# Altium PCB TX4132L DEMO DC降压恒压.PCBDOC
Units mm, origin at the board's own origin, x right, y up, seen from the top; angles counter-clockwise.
Board outline 40.15 x 29.25 mm, 2 copper layers (TopLayer, BottomLayer); 27 components, 14 nets, 64 pads, 16 vias.
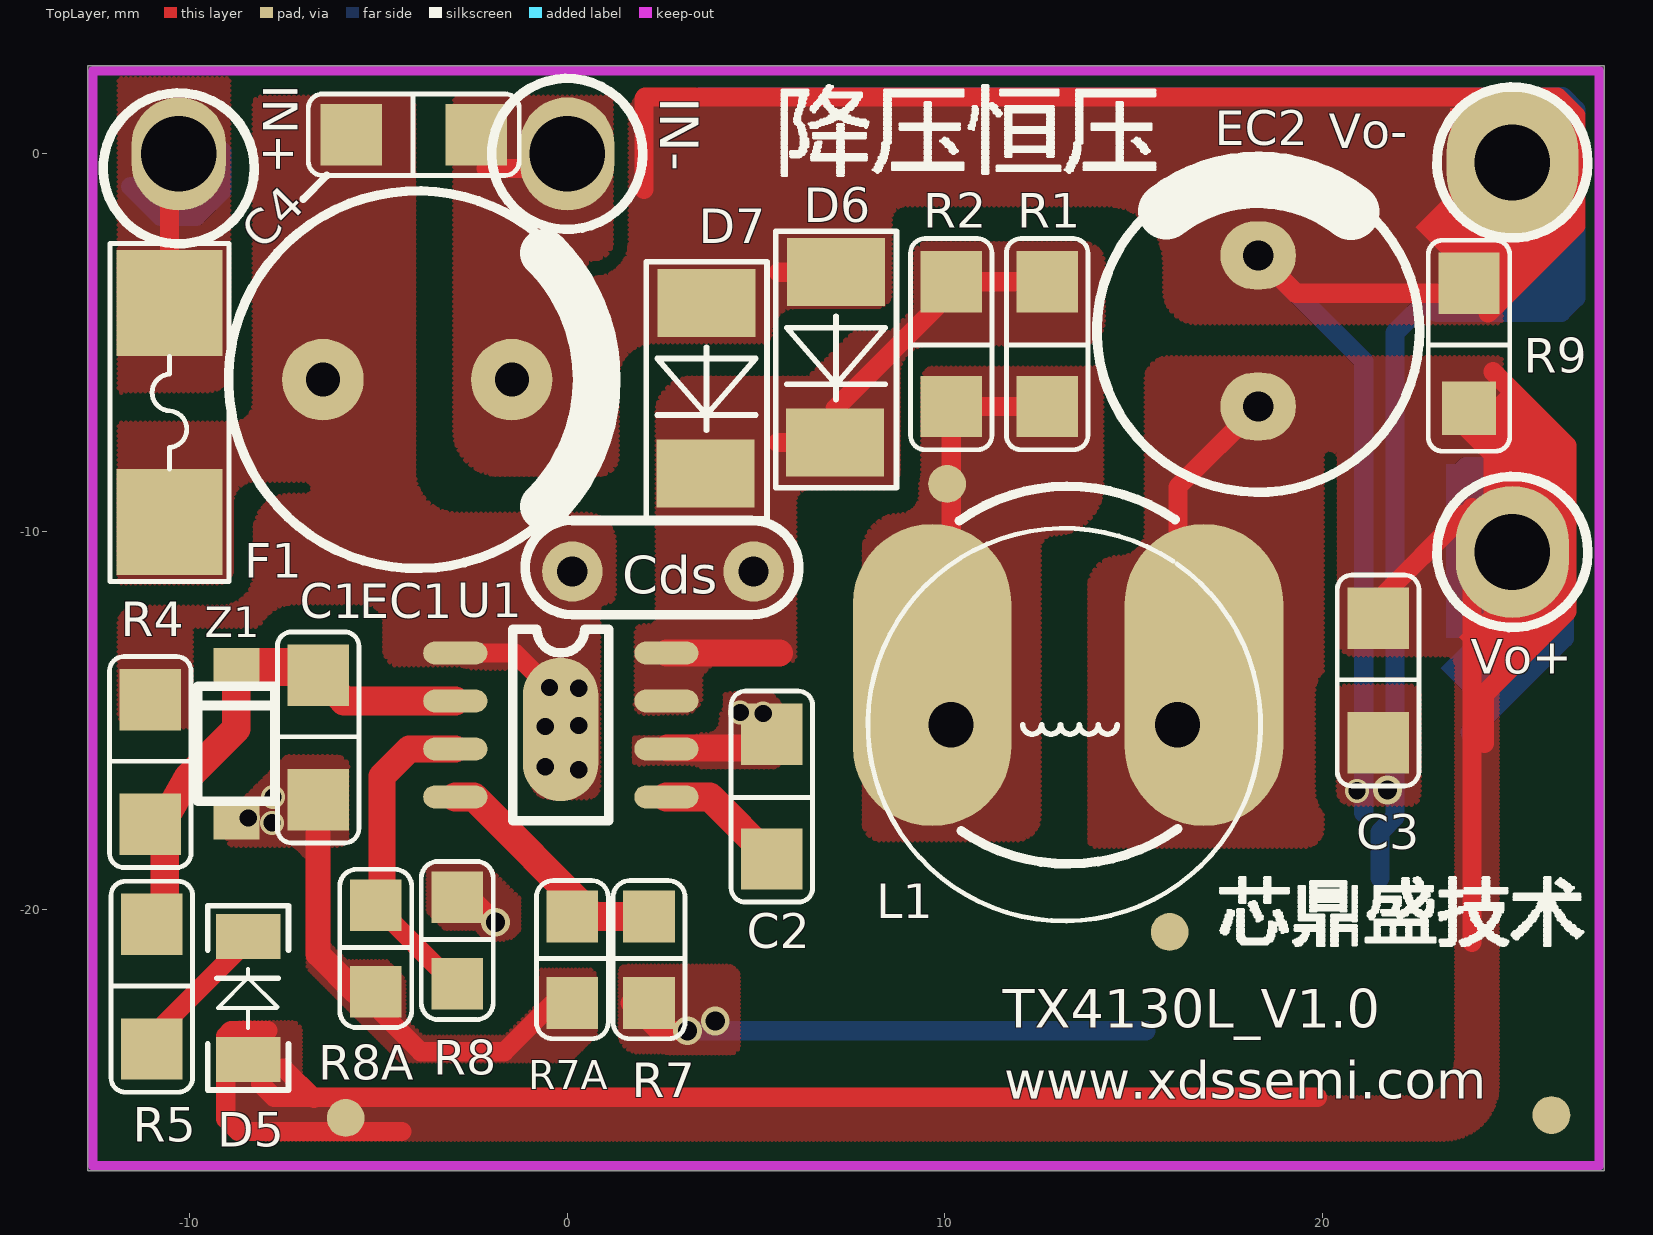
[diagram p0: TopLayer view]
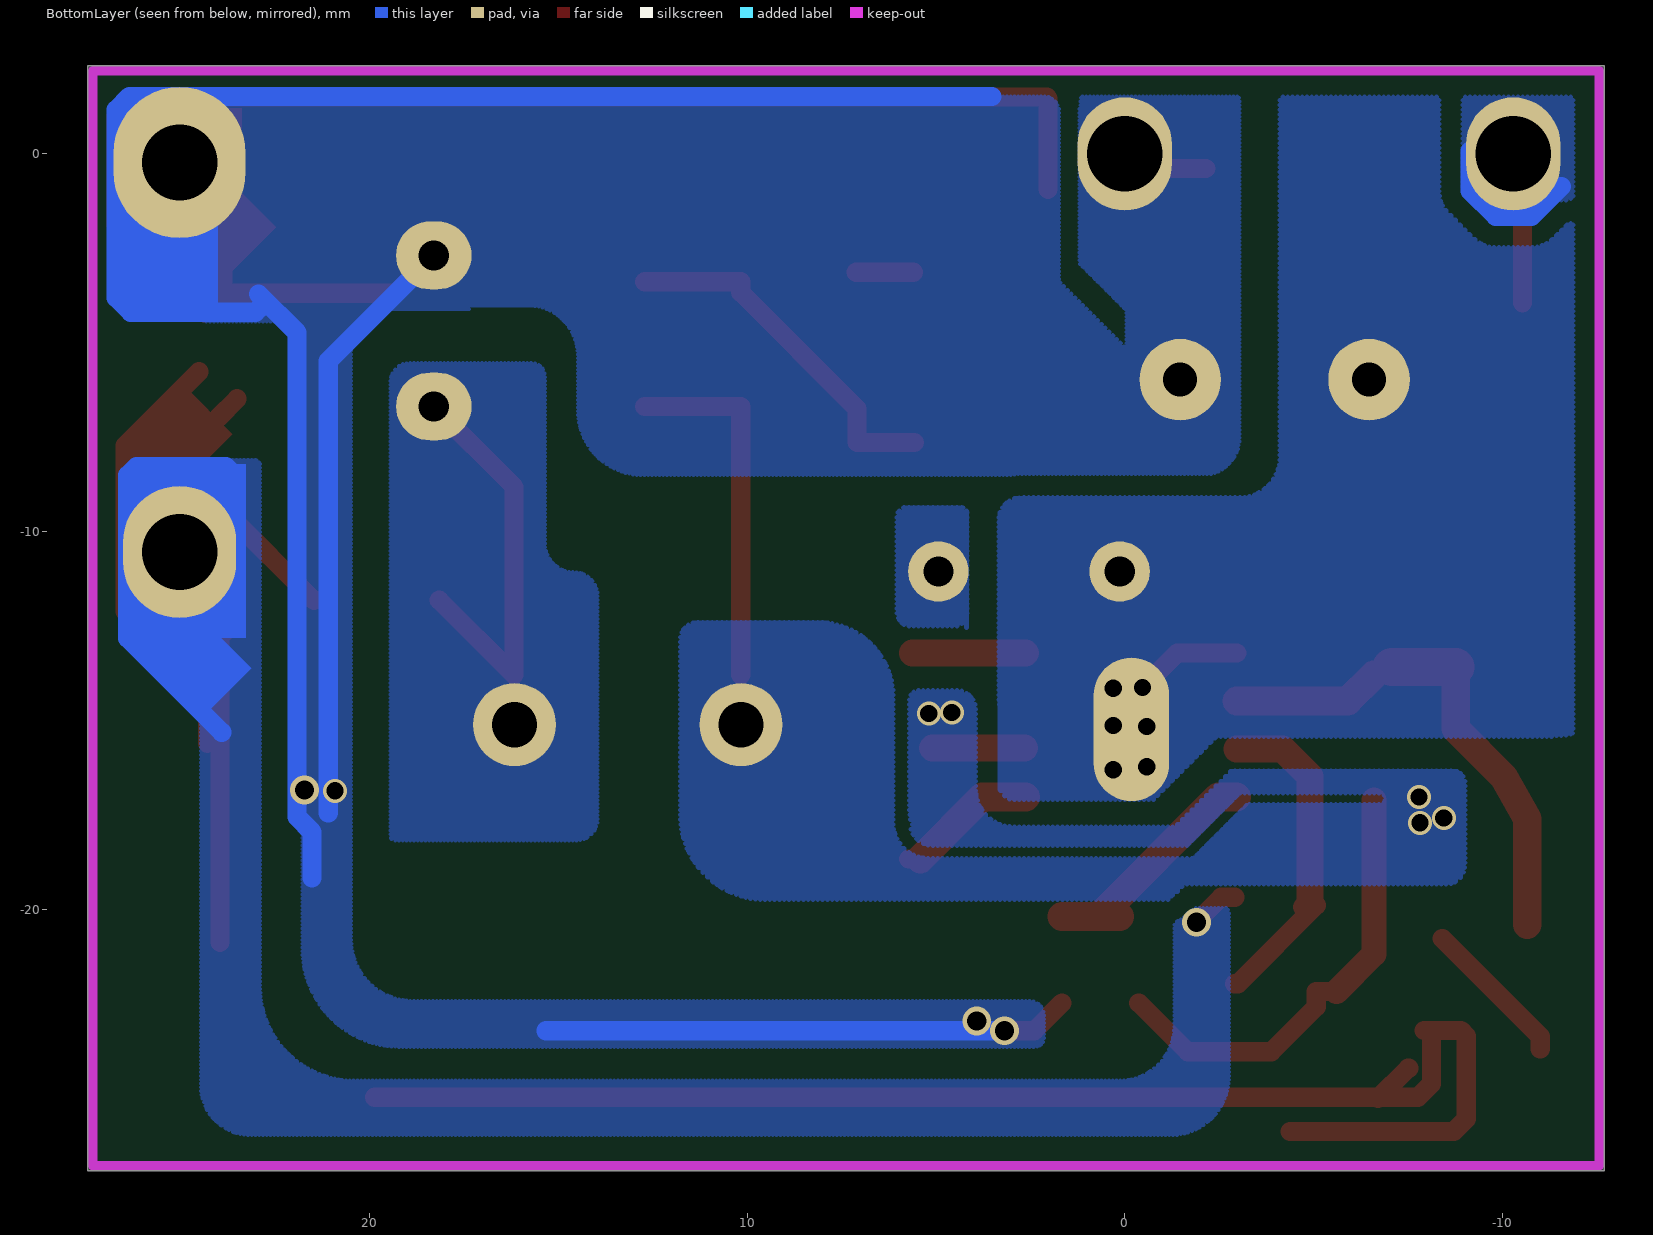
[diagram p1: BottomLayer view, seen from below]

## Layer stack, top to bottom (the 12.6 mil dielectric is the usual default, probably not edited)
TopLayer: signal copper 0.0356
Dielectric: dielectric 0.32, FR-4, Dk 4.8
BottomLayer: signal copper 0.0356

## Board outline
-12.692,-26.924 27.454,-26.924 27.454,2.33 -12.692,2.33

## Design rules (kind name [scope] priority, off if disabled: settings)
Clearance [All] p1: gap=0.508
ComponentClearance [All] p1 off: gap=0.254 collisioncheckmode=3 verticalgap=0.254 showdistances=FALSE
PolygonConnect [All] p1: connectstyle=Direct reliefconductorwidth=0.254 reliefentries=4 polygonreliefangle="90 Angle"
RoutingVias [All] p1: holewidth=0.711 width=1.27 viastyle="Through Hole" minholewidth=0.711 minwidth=1.27 maxholewidth=0.711 maxwidth=1.27
SilkscreenOverComponentPads [All] p1: minsilkscreentomaskgap=0.254
SolderMaskExpansion [All] p1: expansion=0.102
TestPointUsage [All] p1: valid=0 allowmultiple=FALSE
Testpoint [All] p1: side=15 testpointundercomponent=TRUE minsize=1.016 maxsize=2.54 preferedsize=1.524 minholesize=0.508 maxholesize=1.016 preferedholesize=0.813 testpointgrid=0.025 style=1023 order=0-112345678
Width [All] p1: maxlimit=0.508 minlimit=0.508 preferedwidth=0.508
22 further rules are at their usual default settings.

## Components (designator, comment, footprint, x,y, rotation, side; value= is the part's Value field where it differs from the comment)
C1 "" R1206#1 -6.596,-13.8 r0 top
C2 "" R1206#1 5.418,-18.669 r180 top
C3 "" R1206#1 21.471,-12.292 r0 top
C4 "" R1206#1 -5.715,0.508 r90 top
Cds "" CRCD 0.135,-11.057 r0 top
D5 "" S4148 -8.45,-23.975 r180 top
D6 "" SMB 7.12,-3.132 r270 top
D7 "" SMB 3.691,-3.945 r270 top
EC1 "" c10*16 -6.469,-5.977 r0 top
EC2 "" C8*12 18.296,-6.688 r0 top
F1 "" F05 -10.533,-3.945 r270 top
IN+ "" pad#1 -10.287,-0.381 r0 top
L1 "" CD105 9.66,-13.8 r0 top
R1 "" R1206#1 12.708,-6.688 r180 top
R2 "" R1206#1 10.168,-6.688 r180 top
R4 "" R1206#1 -11.041,-14.451 r0 top
R5 "" R1206#1 -11,-20.4 r0 top
R7 "" r0805 2.167,-20.193 r180 top
R7A "" r0805 0.135,-20.193 r180 top
R8 "" r0805 -2.913,-19.685 r180 top
R8A "" r0805 -5.072,-19.896 r180 top
R9 "" R1206#2 23.876,-3.429 r0 top
U1 "" SOP8 -2.964,-13.216 r90 top
Vo+ "" pad#2 25.027,-10.541 r90 top
Vo- "" pad#3 23.503,-0.227 r90 top
Z1 "" SOD123 -8.763,-17.653 r90 top
? "" L10*16 10.16,-15.113 r0 top

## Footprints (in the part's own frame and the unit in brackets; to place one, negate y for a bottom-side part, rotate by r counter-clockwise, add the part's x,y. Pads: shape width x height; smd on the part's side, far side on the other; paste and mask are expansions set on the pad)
C8*12 [mm]
  oval 2x1.8 hole 0.8: 1(0,0) 2(0,4)
  silkscreen extent -4.27,-2.27 4.27,6.27
c10*16 [mil]
  round 85 hole 35.43: 1(0,0) 2(196.85,0)
  silkscreen extent -98,-197 295,197
CD105 [mm]
  oval 4.2x8 smd: 1(0,0) 2(7.2,0)
  silkscreen extent 0.72,-5 6.51,5
CRCD [mm]
  round 1.6 hole 0.8: 1(0,0) 2(4.8,0)
  silkscreen extent -1.25,-1.15 6,1.35
F05 [mm]
  rect 2.8x2.8 smd: 1(0,0) 2(5.8,0)
  silkscreen extent -1.57,-1.57 7.37,1.57
L10*16 [mm]
  round 2.2 hole 1.2: 1(0,0) 2(6,0)
  silkscreen extent -2.2,-5.2 8.2,5.2
pad#1 [mm]
  oval 2.5x3 hole 2: 1(0,0.381)
pad#2 [mm]
  oval 3.5x3 hole 2: 1(0,0)
pad#3 [mm]
  oval 4x3.5 hole 2: 1(0,-1.524)
r0805 [mil]
  rect 54x54 smd: 1(0,0) 2(0,90)
  silkscreen extent -38,-38 38,128
R1206#1 [mil]
  rect 64x64 smd: 1(0,0) 2(0,-130)
  silkscreen extent -42,-175 42,45
R1206#2 [mil]
  rect 64x64 smd: 1(0,0)
  rect 56x56 smd: 2(0,-130)
  silkscreen extent -42,-175 42,45
S4148 [mil]
  rect 67x47 smd: 1(0,0) 2(0,-128)
  silkscreen extent -42,-160 42,32
SMB [mm]
  rect 1.8x2.6 smd: 1(0,0) 2(4.511,-0.031)
  silkscreen extent -1.09,-1.6 5.71,1.6
SOD123 [mm]
  rect 1x1.22 smd: 1(0,0) 2(4.064,0)
  silkscreen extent 0.51,-1.02 3.56,1.02
SOP8 [mil]
  oval 24x66.93 smd: 1(0,0) 2(-50,0) 3(-100,0) 4(-150,0) 5(-150,-220) 6(-100,-220) 7(-50,-220) 8(0,-220)
  round 27.56 on Top Overlay: ""(-22.13,-84.65)
  silkscreen extent -175,-160 25,-60

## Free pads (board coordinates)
  oval 2x3.8 all layers, no hole: 0(-0.178,-15.239)
  oval 2.5x3 hole 2: 0(0,0)
  round 1 smd: 1(-5.867,-25.527) 1(10.058,-8.738) 1(15.951,-20.599) 1(26.06,-25.451)

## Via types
v1: diameter 0.635, hole 0.457, TopLayer to BottomLayer, 6 vias
v2: diameter 0.889, hole 0.457, TopLayer to BottomLayer, 6 vias
v3: diameter 0.762, hole 0.508, TopLayer to BottomLayer, 4 vias

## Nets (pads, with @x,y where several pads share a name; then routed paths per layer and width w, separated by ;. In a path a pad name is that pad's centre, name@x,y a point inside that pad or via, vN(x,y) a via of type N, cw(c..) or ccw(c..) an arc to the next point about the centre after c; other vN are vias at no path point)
GND: C3.2 C4.2 D6.1 D7.1 EC1.2 EC2.2 pad.0@0,0 R7.2 R9.1 Vo-.1 | length 124.5
  TopLayer w0.508: -2.151,-0.389 pad.0@0.465,-0.389 ; R7.2@1.659,-22.479 2.396,-23.216 v3(3.183,-23.216) ; 2.032,-0.94 2.032,1.471 2.065,1.504 26.215,1.504 26.487,1.233 26.703,1.016 26.703,-1.897 R9.1@24.384,-4.216 ; 5.596,-3.132 D6.1 ; EC2.2 19.299,-3.691 R9.1@24.011,-3.691 ; R9.1@23.884,-3.564 Vo-.1@23.884,-1.1
  BottomLayer w0.508: v3(3.183,-23.216) 15.324,-23.216 ; 3.517,1.518 26.354,1.518 26.703,1.168 26.703,-3.81 26.322,-4.191 23.021,-4.191 22.919,-4.089 ; EC2.2 21.09,-5.482 21.09,-17.45 ; 21.519,-19.177 21.519,-17.953 21.919,-17.553 21.919,-4.73 22.936,-3.713
  other v1: 20.912,-16.864
  other v3: 3.92,-22.962 21.719,-16.84
NetC5_1: R7.1 R7A.1 U1.4 | length 6.5
  TopLayer w0.762: U1.4 -2.473,-17.026 R7A.1@0.694,-20.193 ; R7A.1 R7.1@1.659,-20.193
NetD1_2: 
NetD5_1: ?.2 C3.1 D5.1 EC2.1 L1.2 pad.1@-5.867,-25.527 R8.1 R9.2 Vo+.1 | length 88.9
  TopLayer w0.508: D5.1@-8.12,-23.452 -8.12,-24.621 -7.764,-24.976 19.863,-24.976 ; -7.925,-23.213 -8.901,-23.213 -9.042,-23.354 -9.042,-25.552 -8.712,-25.883 -4.381,-25.883 ; -7.518,-24.213 -7.506,-24.213 -6.706,-25.013 ; R8.1 -2.557,-19.685 v3(-1.897,-20.345) ; L1.2@18.149,-11.819 16.168,-13.8 16.168,-8.816 EC2.1 ; C3.1@21.471,-11.819 23.757,-9.533 Vo+.1@24.011,-9.533 ; R9.2@23.503,-6.485 R9.2@24.011,-6.993 ; 23.96,-20.879 Vo+.1@23.96,-9.371 ; 24.29,-15.613 24.29,-14.3 26.475,-12.116 26.475,-7.73 24.511,-5.766
  BottomLayer w0.508: 23.519,-8.56 23.798,-8.28 26.068,-8.28 26.17,-8.28 26.399,-8.509 26.399,-12.824 23.909,-15.313
NetQ1_3: Cds.2 D6.2 D7.2 R1.2 R2.2 U1.7 U1.8 | length 12.6
  TopLayer w0.508: 5.565,-7.643 D6.2 7.089,-6.745 10.168,-3.666 R2.2 R1.2
  TopLayer w0.711: U1.8 5.621,-13.216
NetR4A_1: C1.1 R4.2 R5.1 U1.2 Z1.2 | length 13.7
  TopLayer w0.508: C1.1@-7.061,-13.589 -6.85,-13.8 C1.1
  TopLayer w0.76: -10.025,-16.485 -8.763,-15.223 Z1.2
  TopLayer w0.762: R5.1@-10.66,-20.404 -10.66,-17.61 -10.025,-16.485 ; C1.1 -5.91,-14.486 U1.2
  TopLayer w1: Z1.2 C1.1@-7.061,-13.589
NetR5_2: D5.2 R5.2 | length 4
  TopLayer w0.508: R5.2 -11,-23.37 D5.2@-8.407,-20.777
NetR6_1: 
NetR6_2: C2.1 U1.5 | length 3.8
  TopLayer w0.508: C2.1 C2.1@5.723,-18.669
  TopLayer w0.76: U1.5 3.775,-17.026 C2.1
NetR8A_1: R8.2 R8A.1 U1.3 | length 8.9
  TopLayer w0.508: R8A.1@-4.709,-19.939 -4.752,-19.896 R8A.1 -2.997,-21.971 R8.2
  TopLayer w0.711: R8A.1@-4.907,-19.731 -4.907,-16.48 -4.183,-15.756 U1.3
NetU1_1: C4.1 Cds.1 EC1.1 F1.2 pad.0@-0.178,-15.239 R4.1 U1.1 | length 2.9
  TopLayer w0.508: U1.1 -1.388,-13.216 v2(-0.472,-14.132)
  other v2: 0.305,-16.305 -0.584,-16.229 -0.584,-15.162 0.305,-15.137 0.305,-14.146
NetVAC1_1: F1.1 IN+.1 | length 8.3
  TopLayer w0.508: F1.1 -10.533,-0.389 IN+.1@-10.025,0.119
  BottomLayer w0.508: -11.557,-0.864 -10.77,-1.651 -9.822,-1.651 -9.144,-0.973 IN+.1@-9.144,0.076
NetVAC2_1: 
SGND: ?.1 C1.2 C2.2 L1.1 pad.1@10.058,-8.738 R1.1 R2.1 R7A.2 R8A.2 U1.6 Z1.1 | length 24.3
  TopLayer w0.508: R8A.2@-5.605,-22.182 R8A.2 -5.072,-22.581 -3.878,-23.774 -1.668,-23.774 R7A.2@-0.373,-22.479 ; U1.6 U1.6@2.65,-15.731 ; L1.1@10.168,-13.8 R2.1 R1.1
  TopLayer w0.66: C1.2 -6.596,-21.192 R8A.2@-5.605,-22.182
  TopLayer w0.711: U1.6@2.65,-15.731 C2.2@5.088,-15.731
  other v1: -7.815,-17.712 -8.45,-17.585 -7.79,-17.026 5.19,-14.816 4.58,-14.791
pads on no net: U1.

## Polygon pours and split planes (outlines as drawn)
GND on TopLayer "TopLayer-GND 4" (hatched 90Degree grid 0.1 track 0.1, remove dead copper, pour order 1015): 3.412,-21.488 4.224,-21.488 cw(c4.224,-21.819) 4.555,-21.819 4.555,-23.597 cw(c4.326,-23.597) 4.326,-23.825 2.726,-23.825 cw(c2.726,-23.343) 2.243,-23.343 2.243,-21.488
GND on TopLayer "TopLayer-GND 3" (hatched 90Degree grid 0.1 track 0.1, remove dead copper, pour order 1014): 1.38,-21.717 1.38,-23.292 ccw(c1.888,-23.292) 1.888,-23.8 3.615,-23.8 ccw(c3.615,-23.495) 3.92,-23.495 3.92,-21.768 ccw(c3.64,-21.768) 3.64,-21.488 1.557,-21.488 cw(c1.38,-21.488) 1.38,-21.666 cw(c1.557,-21.666) 1.557,-21.488 1.583,-21.488
SGND on TopLayer "TopLayer-SGND 3" (hatched 90Degree grid 0.1 track 0.1, remove dead copper, pour order 1013): -0.779,-21.717 -0.779,-22.504 -1.643,-23.368 -3.827,-23.368 -4.31,-22.885 -4.31,-21.844 -4.793,-21.361 -5.859,-21.361 -6.317,-20.904 -6.317,-18.007 -7.536,-18.007 -6.875,-18.668 -6.875,-21.565 -4.412,-24.028 0.059,-24.028 0.77,-23.317 0.77,-21.742 0.618,-21.59 -0.678,-21.59 -0.779,-21.692
NetD5_1 on TopLayer "TopLayer-NetD5_1 2" (hatched 90Degree grid 0.1 track 0.1, remove dead copper, pour order 1012): -3.65,-18.821 -2.151,-18.821 -1.262,-19.71 -1.262,-20.549 -1.491,-20.777 -2.176,-20.777 -2.43,-20.523 -3.243,-20.523 -3.573,-20.193 -3.7,-20.066 -3.7,-18.847
NetD5_1 on TopLayer "TopLayer-NetD5_1 1" (hatched 90Degree grid 0.1 track 0.1, remove dead copper, pour order 1011): -8.831,-23.216 -8.831,-25.273 ccw(c-7.993,-25.273) -7.993,-26.111 23.198,-26.111 ccw(c23.198,-24.663) 24.646,-24.663 24.646,-12.038 23.732,-12.038 ccw(c23.732,-12.775) 22.995,-12.775 22.995,-13.267 23.241,-13.267 cw(c23.241,-13.554) 23.528,-13.554 23.528,-23.927 cw(c22.487,-23.927) 22.487,-24.968 -6.723,-24.968 cw(c-6.723,-24.638) -7.053,-24.638 -7.053,-23.216 ccw(c-7.282,-23.216) -7.282,-22.987 -8.679,-22.987 ccw(c-8.679,-23.139) -8.831,-23.139
GND on TopLayer "TopLayer-GND 2" (hatched 90Degree grid 0.127 track 0.127, remove dead copper, pour order 1010): -2.989,1.516 -2.989,-7.323 ccw(c-1.821,-7.323) -1.821,-8.492 0.846,-8.492 ccw(c0.846,-8.009) 1.329,-8.009 1.329,-5.926 cw(c2.269,-5.926) 2.269,-4.986 5.139,-4.986 ccw(c5.139,-4.732) 5.393,-4.732 cw(c6.079,-4.732) 6.079,-4.047 8.187,-4.047 ccw(c8.187,-3.666) 8.568,-3.666 8.568,-1.735 cw(c8.949,-1.735) 8.949,-1.354 14.283,-1.354 cw(c14.283,-2.878) 15.807,-2.878 15.807,-3.615 ccw(c16.67,-3.615) 16.67,-4.478 24.722,-4.478 ccw(c24.722,-4.174) 25.027,-4.174 25.027,0.957 ccw(c24.24,0.957) 24.24,1.745 2.396,1.745 ccw(c2.396,1.008) 1.659,1.008 1.659,-2.319 cw(c0.694,-2.319) 0.694,-3.285 cw(c0.694,-3.056) 0.465,-3.056 cw(c0.745,-3.056) 0.745,-2.777 ccw(c0.745,-2.345) 1.176,-2.345 1.176,1.364 ccw(c0.846,1.364) 0.846,1.694 -2.888,1.694 ccw(c-2.888,1.592) -2.989,1.592
GND on TopLayer "TopLayer-GND 1" (hatched 90Degree grid 0.127 track 0.127, remove dead copper, pour order 1009): -3.319,1.389
NetD5_1 on TopLayer "TopLayer-NetD5_1" (hatched 90Degree grid 0.127 track 0.127, remove dead copper, pour order 1008): 13.826,-17.28 13.826,-11.463 cw(c14.613,-11.463) 14.613,-10.676 ccw(c14.613,-9.965) 15.324,-9.965 15.324,-5.977 cw(c15.908,-5.977) 15.908,-5.393 24.824,-5.393 cw(c24.824,-5.647) 25.078,-5.647 25.078,-12.835 cw(c24.646,-12.835) 24.646,-13.267 20.811,-13.267 cw(c20.811,-12.886) 20.43,-12.886 20.43,-8.085 ccw(c20.176,-8.085) 20.176,-7.831 ccw(c20.176,-8.009) 19.998,-8.009 19.998,-17.839 cw(c19.49,-17.839) 19.49,-18.347 14.003,-18.347 cw(c14.003,-18.169) 13.826,-18.169
SGND on TopLayer "TopLayer-SGND 2" (hatched 90Degree grid 0.127 track 0.127, remove dead copper, pour order 1007): 7.857,-16.874 7.857,-10.498 cw(c8.796,-10.498) 8.796,-9.558 ccw(c8.796,-9) 9.355,-9 9.355,-6.129 cw(c9.914,-6.129) 9.914,-5.571 13.724,-5.571 cw(c13.724,-6.002) 14.156,-6.002 14.156,-8.822 cw(c12.911,-8.822) 12.911,-10.066 ccw(c12.911,-10.473) 12.505,-10.473 12.505,-17.534 cw(c11.87,-17.534) 11.87,-18.169 8.314,-18.169 cw(c8.314,-17.712) 7.857,-17.712
SGND on TopLayer "TopLayer-SGND 1" (hatched 90Degree grid 0.127 track 0.127, remove dead copper, pour order 1006): 1.938,-15.375 3.691,-15.375 ccw(c3.691,-14.994) 4.072,-14.994 4.072,-14.511 cw(c4.301,-14.511) 4.301,-14.283 5.24,-14.283 cw(c5.24,-14.689) 5.647,-14.689 5.647,-16.035 cw(c5.444,-16.035) 5.444,-16.239 1.964,-16.239 cw(c1.964,-16.035) 1.761,-16.035 1.761,-15.527 cw(c1.913,-15.527) 1.913,-15.375
NetQ1_3 on TopLayer "TopLayer-NetQ1_3" (hatched 90Degree grid 0.127 track 0.127, remove dead copper, pour order 1005): 1.811,-14.537 1.811,-12.683 cw(c2.015,-12.683) 2.015,-12.479 2.192,-12.479 ccw(c2.192,-12.302) 2.37,-12.302 2.37,-6.866 cw(c3.31,-6.866) 3.31,-5.926 6.383,-5.926 7.577,-4.732 8.568,-4.732 9.203,-4.097 9.203,-2.675 cw(c9.508,-2.675) 9.508,-2.37 13.673,-2.37 cw(c13.673,-2.904) 14.207,-2.904 14.207,-4.428 cw(c13.597,-4.428) 13.597,-5.037 9.584,-5.037 ccw(c9.584,-5.85) 8.771,-5.85 8.771,-8.415 cw(c8.339,-8.415) 8.339,-8.847 6.409,-8.847 ccw(c6.409,-9.228) 6.028,-9.228 6.028,-13.419 3.92,-13.419 3.539,-13.8 3.539,-14.511 3.234,-14.816 1.938,-14.816 1.786,-14.664 1.786,-14.486
SGND on TopLayer "TopLayer-SGND" (hatched 90Degree grid 0.127 track 0.127, remove dead copper, pour order 1004): -9.009,-17.534 -7.434,-15.959 -6.113,-15.959 cw(c-6.113,-16.289) -5.783,-16.289 -5.783,-17.991 cw(c-6.113,-17.991) -6.113,-18.321 -8.806,-18.321 cw(c-8.806,-18.118) -9.009,-18.118
GND on TopLayer "TopLayer-GND" (hatched 90Degree grid 0.127 track 0.127, remove dead copper, pour order 1003): 20.404,-14.232 20.404,-16.848 ccw(c20.785,-16.848) 20.785,-17.229 22.309,-17.229 ccw(c22.309,-16.975) 22.563,-16.975 22.563,-14.334 ccw(c22.309,-14.334) 22.309,-14.08 20.582,-14.08 ccw(c20.582,-14.257) 20.404,-14.257
NetU1_1 on TopLayer "TopLayer-NetU1_1" (hatched 90Degree grid 0.127 track 0.127, remove dead copper, pour order 1002): -11.955,-7.12 -8.831,-7.12 ccw(c-8.831,-6.587) -8.298,-6.587 -8.298,1.211 cw(c-7.663,1.211) -7.663,1.846 -4.691,1.846 cw(c-4.691,1.211) -4.056,1.211 -4.056,-8.39 ccw(c-2.913,-8.39) -2.913,-9.533 0.491,-9.533 cw(c0.491,-10.295) 1.253,-10.295 1.253,-11.641 cw(c0.999,-11.641) 0.999,-11.895 ccw(c0.999,-12.048) 0.846,-12.048 0.846,-16.721 cw(c0.516,-16.721) 0.516,-17.051 -0.475,-17.051 cw(c-0.475,-16.594) -0.932,-16.594 -0.932,-13.953 ccw(c-1.262,-13.953) -1.262,-13.622 -4.31,-13.622 cw(c-4.31,-13.089) -4.843,-13.089 -4.843,-12.454 ccw(c-5.402,-12.454) -5.402,-11.895 -7.206,-11.895 ccw(c-7.206,-12.962) -8.272,-12.962 -8.272,-13.445 -10,-15.172 -11.473,-15.172 cw(c-11.473,-14.765) -11.879,-14.765 -11.879,-12.479 cw(c-11.397,-12.479) -11.397,-11.997 -9.187,-11.997 ccw(c-9.187,-11.082) -8.272,-11.082 -8.272,-9.965 cw(c-7.333,-9.965) -7.333,-9.025 -6.901,-9.025 ccw(c-6.901,-8.873) -6.748,-8.873 ccw(c-6.977,-8.873) -6.977,-8.644 -8.272,-8.644 ccw(c-8.272,-9.254) -8.882,-9.254 -8.882,-11.006 cw(c-9.238,-11.006) -9.238,-11.362 -12.082,-11.362 cw(c-12.082,-11.209) -12.235,-11.209 -12.235,-7.45 cw(c-11.905,-7.45) -11.905,-7.12
NetD1_2 on TopLayer "TopLayer-NetD1_2" (hatched 90Degree grid 0.127 track 0.127, remove dead copper, pour order 1001): -11.879,-7.272
NetVAC1_1 on TopLayer "TopLayer-NetVAC1_1" (hatched 90Degree grid 0.127 track 0.127, remove dead copper, pour order 1000): -12.336,2.303 -12.336,-5.748 ccw(c-11.803,-5.748) -11.803,-6.282 -9.517,-6.282 ccw(c-9.517,-5.723) -8.958,-5.723 -8.958,2.126 cw(c-8.958,2.354) -9.187,2.354 cw(c-9.187,2.126) -8.958,2.126 ccw(c-9.212,2.126) -9.212,2.38 -12.311,2.38
NetD5_1 on BottomLayer "BottomLayer-NetD5_1 1" (hatched 90Degree grid 0.1 track 0.1, remove dead copper, pour order 1024): 15.35,-6.147 15.35,-10.312 cw(c14.588,-10.312) 14.588,-11.074 ccw(c14.588,-11.709) 13.953,-11.709 13.953,-17.602 ccw(c14.537,-17.602) 14.537,-18.186 19.337,-18.186 ccw(c19.337,-18.085) 19.439,-18.085 19.439,-6.02 ccw(c18.956,-6.02) 18.956,-5.537 15.705,-5.537 ccw(c15.705,-5.893) 15.35,-5.893
GND on BottomLayer "BottomLayer-GND 1" (hatched 90Degree grid 0.1 track 0.1, remove dead copper, pour order 1023): 1.202,1.245 1.202,-2.896 -0.043,-4.14 -0.043,-5.156 1.735,-3.378 1.735,1.118 cw(c2.142,1.118) 2.142,1.524 24.036,1.524 cw(c24.036,0.914) 24.646,0.914 24.646,-4.039 cw(c24.24,-4.039) 24.24,-4.445 22.055,-4.445 ccw(c22.055,-4.724) 21.776,-4.724 21.776,-21.057 cw(c19.185,-21.057) 19.185,-23.647 2.37,-23.647 cw(c2.37,-23.419) 2.142,-23.419 2.142,-22.809 cw(c2.523,-22.809) 2.523,-22.428 18.855,-22.428 ccw(c18.855,-20.803) 20.48,-20.803 20.48,-5.105 ccw(c19.49,-5.105) 19.49,-4.115 17.356,-4.115 17.356,-4.013 15.807,-4.013 ccw(c15.807,-5.334) 14.486,-5.334 14.486,-6.782 cw(c12.759,-6.782) 12.759,-8.509 -2.049,-8.509 cw(c-2.049,-7.518) -3.04,-7.518 -3.04,1.422 cw(c-2.862,1.422) -2.862,1.6 0.973,1.6 cw(c0.973,1.397) 1.176,1.397 1.176,1.245
NetD5_1 on BottomLayer "BottomLayer-NetD5_1" (hatched 90Degree grid 0.1 track 0.1, remove dead copper, pour order 1022): 22.893,-8.763 22.893,-22.047 cw(c20.404,-22.047) 20.404,-24.536 0.135,-24.536 cw(c0.135,-23.089) -1.313,-23.089 -1.313,-20.422 ccw(c-1.872,-20.422) -1.872,-19.863 -2.507,-19.863 ccw(c-2.507,-20.117) -2.761,-20.117 -2.761,-24.435 ccw(c-1.211,-24.435) -1.211,-25.984 23.147,-25.984 ccw(c23.147,-24.663) 24.468,-24.663 24.468,-8.407 ccw(c24.163,-8.407) 24.163,-8.103 23.046,-8.103 ccw(c23.046,-8.255) 22.893,-8.255
NetQ1_3 on BottomLayer "BottomLayer-NetQ1_3" (hatched 90Degree grid 0.127 track 0.127, remove dead copper, pour order 1021): 4.174,-9.584 4.174,-12.2 4.199,-12.2 ccw(c4.504,-12.2) 4.504,-12.505 5.672,-12.505 ccw(c5.672,-12.149) 6.028,-12.149 6.028,-9.609 ccw(c5.774,-9.609) 5.774,-9.355 4.351,-9.355 ccw(c4.351,-9.533) 4.174,-9.533
NetU1_1 on BottomLayer "BottomLayer-NetU1_1 1" (hatched 90Degree grid 0.127 track 0.127, remove dead copper, pour order 1020): -11.905,-15.756
GND on BottomLayer "BottomLayer-GND" (hatched 90Degree grid 0.127 track 0.127, remove dead copper, pour order 1019): -1.287,-8.492
NetVAC1_1 on BottomLayer "BottomLayer-NetVAC1_1" (hatched 90Degree grid 0.127 track 0.127, remove dead copper, pour order 1018): -12.159,1.795 -12.159,-0.643 ccw(c-11.574,-0.643) -11.574,-1.227 -9.263,-1.227 ccw(c-9.263,-0.922) -8.958,-0.922 -8.958,1.618 ccw(c-9.314,1.618) -9.314,1.973 -12.082,1.973 ccw(c-12.082,1.897) -12.159,1.897
SGND on BottomLayer "BottomLayer-SGND" (hatched 90Degree grid 0.127 track 0.127, remove dead copper, pour order 1017): -8.044,-16.34 -2.811,-16.34 -1.338,-17.813 2.954,-17.813 ccw(c2.954,-16.823) 3.945,-16.823 3.945,-14.715 cw(c4.453,-14.715) 4.453,-14.207 5.444,-14.207 cw(c5.444,-14.461) 5.698,-14.461 5.698,-17.432 cw(c4.986,-17.432) 4.986,-18.144 ccw(c4.986,-17.432) 5.698,-17.432 5.698,-17.686 cw(c5.063,-17.686) 5.063,-18.321 -1.643,-18.321 -3.04,-16.924 -6.748,-16.924 ccw(c-6.748,-17.077) -6.901,-17.077 ccw(c-6.748,-17.077) -6.748,-17.229 -3.243,-17.229 -1.821,-18.652 5.19,-18.652 ccw(c5.19,-17.712) 6.129,-17.712 6.129,-14.384 cw(c8.111,-14.384) 8.111,-12.403 11.311,-12.403 cw(c11.311,-12.86) 11.768,-12.86 11.768,-17.509 cw(c9.533,-17.509) 9.533,-19.744 -1.237,-19.744 cw(c-1.237,-19.49) -1.491,-19.49 ccw(c-1.643,-19.49) -1.643,-19.337 -8.501,-19.337 cw(c-8.501,-18.829) -9.009,-18.829 -9.009,-16.645 cw(c-8.704,-16.645) -8.704,-16.34
NetU1_1 on BottomLayer "BottomLayer-NetU1_1" (hatched 90Degree grid 0.127 track 0.127, remove dead copper, pour order 1016): -11.397,-15.426 -2.43,-15.426 -0.754,-17.102 2.904,-17.102 ccw(c2.904,-16.67) 3.335,-16.67 3.335,-9.685 ccw(c2.751,-9.685) 2.751,-9.101 -3.04,-9.101 cw(c-3.04,-8.034) -4.107,-8.034 -4.107,1.44 ccw(c-4.564,1.44) -4.564,1.897 -11.651,1.897 ccw(c-11.651,1.364) -12.184,1.364 -12.184,-14.816 ccw(c-11.6,-14.816) -11.6,-15.4 -11.371,-15.4
NetU1_1 on BottomSolder (hatched 90Degree grid 0.127 track 0.127, remove dead copper): -1.16,-16.086 -2.151,-15.096 -9.873,-15.096 cw(c-9.873,-14.435) -10.533,-14.435 -10.533,-10.219 cw(c-9.517,-10.219) -9.517,-9.203 2.142,-9.203 cw(c2.142,-10.066) 3.005,-10.066 3.005,-16.366 cw(c2.548,-16.366) 2.548,-16.823 -0.729,-16.823 cw(c-0.729,-16.442) -1.11,-16.442 -1.11,-16.188
NetU1_1 on BottomSolder (hatched 90Degree grid 0.127 track 0.127, remove dead copper): -1.237,-15.121

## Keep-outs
KeepOutLayer:
  lines w0.254: -12.565,-26.797 27.327,-26.797 27.327,2.203 -12.565,2.203 -12.565,-26.797

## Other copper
TopLayer:
  region net GND: 24.555,-4.045 26.834,-1.767 24.737,0.33 22.458,-1.948
  region net GND: 26.703,-1.897 26.703,1.219 23.368,1.219 23.368,-1.897
  region net NetD5_1: 26.475,-7.391 24.257,-7.391 24.257,-12.116 26.475,-12.116
  region net NetD5_1: 24.892,-6.147 23.622,-7.417 25.205,-9 26.475,-7.73
  region net NetD5_1: 25.433,-10.973 23.606,-12.8 24.698,-13.892 26.526,-12.065
BottomLayer:
  region net GND: 26.538,-3.976 26.538,1.518 24.011,1.518 24.011,-3.976
  region net NetD5_1: 26.399,-12.824 26.399,-8.213 23.274,-8.213 23.274,-12.824
  region net NetD5_1: 26.476,-12.853 25.179,-11.557 23.123,-13.614 24.419,-14.91
  region net NetVAC1_1: -10.922,-0.533 -10.922,-1.651 -9.822,-1.651 -9.822,-0.533

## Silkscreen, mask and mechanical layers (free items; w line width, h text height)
TopOverlay:
  drawing of 1416 lines, arcs and shapes, not listed
  text "IN-" at 2.464,1.504 h1.02 r270
  text "TX4130L_V1.0" at 11.532,-23.139 h1.02
  text "www.xdssemi.com" at 11.565,-25.013 h1
TopSolder:
  region: -11.76,-7.493 -11.76,-9.093 -9.144,-9.093 -9.144,-7.493
  region: -11.76,-4.928 -11.76,-6.045 -9.195,-6.045 -9.195,-4.928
